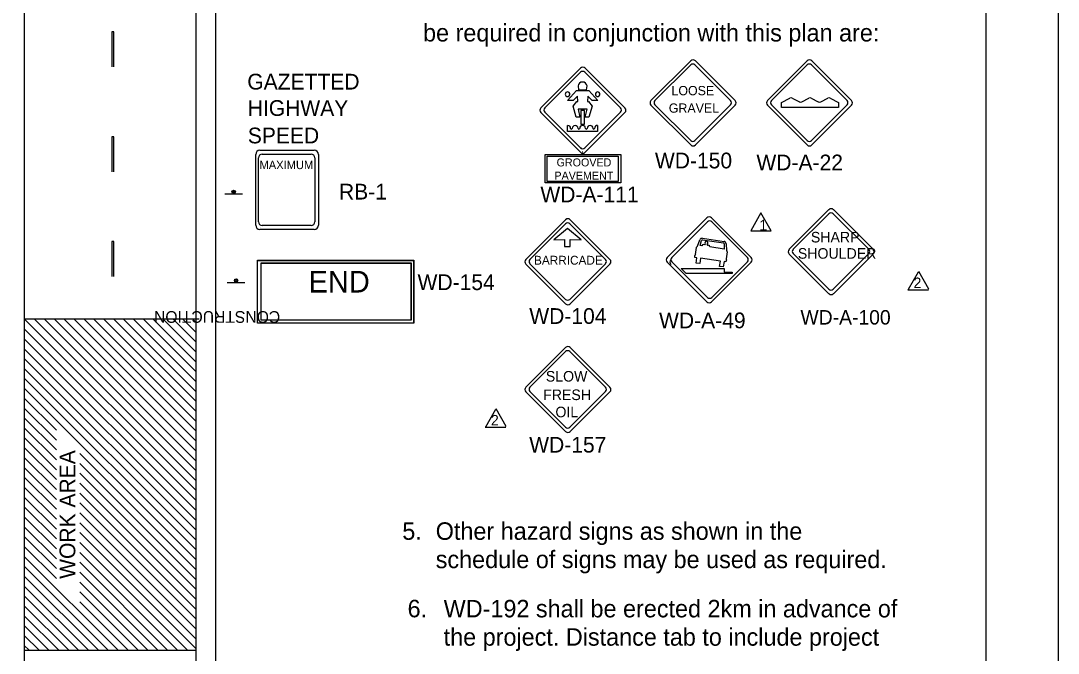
# Model space of a CAD drawing. Extents: x 1372 to 1588, y 125 to 404.
# Drawn here: x 1444.6 to 1588.1, y 244.9 to 332.4 of the extents above; entities that cross this region are included whole.
import ezdxf

# ---------------------------------------------------------------- set-up
doc = ezdxf.new("R2010")
doc.units = 0
for name, color, linetype in [('Level 1', 7, 'Continuous'), ('Level 10', 7, 'Continuous'), ('Level 2', 7, 'Continuous'), ('Level 4', 7, 'Continuous'), ('Level 44', 7, 'Continuous'), ('Level 5', 7, 'Continuous'), ('Level 60', 7, 'Continuous'), ('Level 63', 7, 'Continuous')]:
    doc.layers.add(name, color=color, linetype=linetype)

msp = doc.modelspace()

# ---------------------------------------------------------------- linework, layer by layer
at = {"layer": 'Level 1'}
for p, q in [((1549.79, 321.06), (1550.93, 321.68)), ((1551.27, 321.68), (1552.25, 321.14)), ((1552.58, 321.14), (1553.56, 321.68)), ((1553.9, 321.68), (1554.87, 321.15)), ((1555.21, 321.15), (1556.19, 321.68)), ((1556.53, 321.68), (1557.67, 321.07)), ((1549.79, 320.37), (1549.79, 321.06)), ((1553.73, 320.37), (1549.79, 320.37)), ((1557.67, 320.37), (1553.73, 320.37)), ((1557.67, 321.07), (1557.67, 320.37)), ((1538.16, 301.17), (1538.47, 302.04)), ((1538.55, 301.26), (1538.7, 301.96)), ((1538.84, 302.28), (1541.83, 301.85)), ((1538.86, 302.06), (1541.75, 301.65)), ((1539.16, 301.38), (1539.01, 301.4)), ((1539.01, 301.4), (1539.01, 301.4)), ((1541.86, 301.51), (1541.83, 300.79)), ((1542.12, 301.53), (1542.17, 300.6)), ((1537.9, 300.03), (1538, 300.99)), ((1538.05, 301.1), (1538.16, 301.17)), ((1538.77, 301.22), (1538.55, 301.26)), ((1539.69, 301.3), (1539.54, 301.32)), ((1541.83, 300.79), (1539.87, 301.07)), ((1542.28, 300.39), (1542.11, 299.42)), ((1542.17, 300.6), (1542.26, 300.5)), ((1537.81, 299.62), (1537.81, 299.9)), ((1538.09, 299.59), (1537.81, 299.62)), ((1537.98, 298.84), (1538.09, 299.59)), ((1538.48, 298.77), (1537.98, 298.84)), ((1538.59, 299.52), (1538.48, 298.77)), ((1541.33, 299.13), (1538.59, 299.52)), ((1541.21, 298.38), (1541.33, 299.13)), ((1541.83, 299.06), (1541.71, 298.31)), ((1542.08, 299.02), (1541.83, 299.05)), ((1542.15, 299.28), (1542.08, 299.02)), ((1542.13, 299.32), (1542.15, 299.28)), ((1541.71, 298.31), (1541.21, 298.38))]:
    msp.add_line(p, q, dxfattribs=at)
for points in [[(1546.94, 305.79), (1545.52, 303.32), (1548.36, 303.32)], [(1542.95, 297.41), (1536.61, 297.41), (1535.92, 298.1), (1541.86, 298.1), (1541.86, 297.58), (1542.95, 297.58)]]:
    msp.add_lwpolyline(points, close=True, dxfattribs=at)
for centre, radius, start, end in [((1551.1, 321.37), 0.35, 61.3649, 118.2462), ((1553.73, 321.37), 0.35, 61.6364, 118.4879), ((1556.36, 321.37), 0.35, 61.8639, 118.2174), ((1552.41, 321.45), 0.35, 241.3895, 298.4822), ((1555.04, 321.46), 0.35, 241.6262, 298.2462), ((1538.79, 301.93), 0.344, 81.9388, 160.7571), ((1538.84, 301.92), 0.138, 81.9344, 167.2438), ((1538.98, 301.2), 0.206, 81.9281, 171.9074), ((1539.17, 301.45), 0.0688, 261.9205, 351.8582), ((1539.55, 301.39), 0.0688, 171.8828, 261.9459), ((1541.73, 301.52), 0.138, 356.6105, 81.9338), ((1541.78, 301.51), 0.344, 3.1113, 81.9386), ((1537.77, 300.04), 0.138, 304.1825, 354.8723), ((1538.13, 300.98), 0.138, 124.8259, 174.8703), ((1539.66, 301.1), 0.206, 351.9552, 81.9216), ((1542.15, 300.41), 0.138, 349.4832, 39.2839), ((1534.81, 298.99), 0.457, 135, 225.0349), ((1542.24, 299.4), 0.138, 169.4858, 215.1975)]:
    msp.add_arc(centre, radius, start, end, dxfattribs=at)
msp.add_ellipse((1539.39, 301.64), major_axis=(-0.035, -0.256), ratio=0.783636, start_param=0.628057, end_param=5.591652, dxfattribs=at)
at = {"layer": 'Level 10'}
for p, q in [((1445.05, 372.63), (1445.05, 157.87)), ((1468.76, 372.63), (1468.76, 157.87)), ((1471.51, 372.63), (1471.51, 202.79)), ((1445.05, 291.11), (1469.25, 291.11)), ((1445.05, 291.11), (1468.76, 267.4)), ((1446.42, 291.11), (1468.76, 268.77)), ((1447.79, 291.11), (1468.76, 270.14)), ((1449.16, 291.11), (1468.76, 271.5)), ((1450.53, 291.11), (1468.76, 272.87)), ((1451.89, 291.11), (1468.76, 274.24)), ((1453.26, 291.11), (1468.76, 275.61)), ((1454.63, 291.11), (1468.76, 276.98)), ((1456, 291.11), (1468.76, 278.35)), ((1457.37, 291.11), (1468.76, 279.72)), ((1458.74, 291.11), (1468.76, 281.08)), ((1460.11, 291.11), (1468.76, 282.45)), ((1461.47, 291.11), (1468.76, 283.82)), ((1462.84, 291.11), (1468.76, 285.19)), ((1464.21, 291.11), (1468.76, 286.56)), ((1465.58, 291.11), (1468.76, 287.93)), ((1466.95, 291.11), (1468.76, 289.3)), ((1468.32, 291.11), (1468.76, 290.67)), ((1445.05, 289.74), (1468.76, 266.03)), ((1445.05, 288.37), (1468.76, 264.66)), ((1445.05, 287), (1468.76, 263.29)), ((1445.05, 285.63), (1468.76, 261.93)), ((1445.05, 284.26), (1468.76, 260.56)), ((1445.05, 282.9), (1468.76, 259.19)), ((1445.05, 281.53), (1468.76, 257.82)), ((1445.05, 280.16), (1449.49, 275.72)), ((1445.05, 278.79), (1449.49, 274.35)), ((1445.05, 277.42), (1449.49, 272.99)), ((1445.05, 276.05), (1449.49, 271.62)), ((1445.05, 274.69), (1449.49, 270.25)), ((1445.05, 273.32), (1449.49, 268.88)), ((1445.05, 271.95), (1449.49, 267.51)), ((1452.71, 272.5), (1468.76, 256.45)), ((1445.05, 270.58), (1449.49, 266.14)), ((1452.71, 271.13), (1468.76, 255.08)), ((1445.05, 269.21), (1449.49, 264.77)), ((1452.71, 269.76), (1468.76, 253.71)), ((1452.71, 268.39), (1468.76, 252.34)), ((1445.05, 267.84), (1445.06, 267.83)), ((1445.05, 267.84), (1449.49, 263.4)), ((1452.71, 267.02), (1468.76, 250.97)), ((1445.05, 266.47), (1449.49, 262.04)), ((1452.71, 265.65), (1468.76, 249.61)), ((1445.05, 265.11), (1449.49, 260.67)), ((1452.71, 264.29), (1468.76, 248.24)), ((1445.05, 263.74), (1449.49, 259.3)), ((1452.71, 262.92), (1468.76, 246.87)), ((1445.05, 262.37), (1449.49, 257.93)), ((1452.71, 261.55), (1468.76, 245.5)), ((1445.05, 261), (1449.49, 256.56)), ((1452.71, 260.18), (1467.66, 245.24)), ((1445.05, 259.63), (1449.49, 255.19)), ((1452.71, 258.81), (1466.29, 245.24)), ((1445.05, 258.26), (1458.08, 245.24)), ((1445.05, 256.89), (1456.71, 245.24)), ((1452.71, 257.44), (1464.92, 245.24)), ((1445.05, 255.52), (1455.34, 245.24)), ((1452.71, 256.07), (1463.55, 245.24)), ((1445.05, 254.16), (1453.97, 245.24)), ((1452.71, 254.71), (1462.19, 245.24)), ((1445.05, 252.79), (1452.61, 245.24)), ((1452.71, 253.34), (1460.82, 245.24)), ((1445.05, 251.42), (1451.24, 245.24)), ((1452.71, 251.97), (1459.45, 245.24)), ((1445.05, 250.05), (1449.87, 245.24)), ((1445.05, 248.68), (1448.5, 245.24)), ((1445.05, 247.31), (1447.13, 245.24)), ((1445.05, 245.94), (1445.74, 245.26)), ((1445.16, 245.26), (1468.76, 245.26))]:
    msp.add_line(p, q, dxfattribs=at)
at = {"layer": 'Level 2'}
for p, q in [((1457.15, 330.85), (1457.15, 326.01)), ((1457.44, 330.85), (1457.15, 330.85)), ((1457.44, 326.01), (1457.44, 330.85)), ((1457.15, 316.33), (1457.15, 311.49)), ((1457.44, 316.33), (1457.15, 316.33)), ((1457.44, 311.49), (1457.44, 316.33)), ((1457.15, 301.82), (1457.15, 296.98)), ((1457.44, 301.82), (1457.15, 301.82)), ((1457.44, 296.98), (1457.44, 301.82))]:
    msp.add_line(p, q, dxfattribs=at)
for points in [[(1477.28, 299.25), (1498.94, 299.25), (1498.94, 290.55), (1477.28, 290.55)], [(1477.28, 299.22), (1498.87, 299.22), (1498.87, 290.55), (1477.28, 290.55)], [(1477.79, 298.86), (1498.56, 298.86), (1498.56, 290.95), (1477.79, 290.95)], [(1477.79, 298.83), (1498.5, 298.83), (1498.5, 290.94), (1477.79, 290.94)]]:
    msp.add_lwpolyline(points, close=True, dxfattribs=at)
at = {"layer": 'Level 4'}
for p, q in [((1521.64, 323.36), (1521.72, 322.82)), ((1522.81, 322.82), (1522.89, 323.36)), ((1522.89, 323.36), (1522.89, 323.36)), ((1520.18, 321.35), (1521.42, 322.71)), ((1521.54, 321.92), (1520.94, 321.35)), ((1521.42, 322.71), (1523.11, 322.71)), ((1521.6, 321.19), (1521.54, 321.92)), ((1521.72, 322.82), (1522.81, 322.82)), ((1522.99, 321.92), (1522.93, 321.19)), ((1523.6, 321.35), (1522.99, 321.92)), ((1523.11, 322.71), (1524.36, 321.35)), ((1520.94, 321.35), (1520.18, 321.35)), ((1520.94, 320.54), (1521.45, 321.19)), ((1521.4, 319.05), (1520.94, 320.54)), ((1521.45, 321.19), (1521.6, 321.19)), ((1522.88, 320.16), (1521.66, 320.16)), ((1521.66, 320.16), (1521.89, 319.05)), ((1522.64, 319.05), (1522.88, 320.16)), ((1522.93, 321.19), (1523.08, 321.19)), ((1523.08, 321.19), (1523.6, 320.54)), ((1523.6, 320.54), (1523.14, 319.05)), ((1524.36, 321.35), (1523.6, 321.35)), ((1521.89, 319.05), (1521.4, 319.05)), ((1522.54, 319.94), (1522, 319.94)), ((1522, 319.94), (1522, 318.07)), ((1522.54, 318.07), (1522.54, 319.94)), ((1523.14, 319.05), (1522.64, 319.05)), ((1520.19, 317.05), (1520.19, 317.89)), ((1522, 318.07), (1522.54, 318.07)), ((1524.34, 317.89), (1524.34, 317.05)), ((1524.34, 317.05), (1520.19, 317.05))]:
    msp.add_line(p, q, dxfattribs=at)
for centre, radius, start, end in [((1522.27, 323.27), 0.631, 7.9818, 172.0182), ((1520.18, 322.21), 0.31, 45, 225), ((1520.18, 322.21), 0.31, 45.001, 224.999), ((1520.18, 322.21), 0.31, 224.9986, 45.0014), ((1520.18, 322.21), 0.31, 224.999, 45.001), ((1524.36, 322.21), 0.31, 45, 225), ((1524.36, 322.21), 0.31, 45.001, 224.999), ((1524.36, 322.21), 0.31, 224.9986, 45.0014), ((1524.36, 322.21), 0.31, 224.999, 45.001), ((1520.72, 317.48), 0.109, 180, 0), ((1521.75, 317.48), 0.109, 180, 0), ((1522.27, 317.48), 0.407, 0.7691, 179.2309), ((1522.78, 317.48), 0.109, 180, 0), ((1523.3, 317.48), 0.407, 0.7691, 179.2309), ((1523.81, 317.48), 0.109, 180, 0), ((1524.33, 317.48), 0.407, 88.4721, 179.2361)]:
    msp.add_arc(centre, radius, start, end, dxfattribs=at)
for centre, end_param in [((1520.2, 317.48), 4.739059), ((1521.23, 317.48), 6.283185)]:
    msp.add_ellipse(centre, major_axis=(-0.407, 0), ratio=0.986667, start_param=3.141593, end_param=end_param, dxfattribs=at)
at = {"layer": 'Level 44'}
for p, q in [((1521.99, 325.8), (1516.5, 320.32)), ((1528.12, 320.32), (1522.64, 325.8)), ((1537.22, 326.81), (1531.72, 321.33)), ((1532.27, 321.32), (1537.22, 326.26)), ((1537.8, 326.26), (1542.74, 321.32)), ((1543.35, 321.33), (1537.87, 326.81)), ((1553.33, 326.81), (1547.83, 321.33)), ((1548.38, 321.32), (1553.33, 326.26)), ((1553.91, 326.26), (1558.85, 321.32)), ((1559.46, 321.33), (1553.98, 326.81)), ((1517.05, 320.31), (1521.99, 325.25)), ((1522.57, 325.25), (1527.51, 320.31)), ((1531.72, 320.68), (1537.22, 315.19)), ((1531.73, 320.68), (1531.72, 320.68)), ((1537.22, 315.8), (1532.27, 320.74)), ((1542.74, 320.74), (1537.8, 315.8)), ((1537.87, 315.19), (1543.35, 320.68)), ((1547.83, 320.68), (1553.33, 315.19)), ((1547.84, 320.68), (1547.83, 320.68)), ((1553.33, 315.8), (1548.38, 320.74)), ((1558.85, 320.74), (1553.91, 315.8)), ((1553.98, 315.19), (1559.46, 320.68)), ((1516.5, 319.67), (1521.99, 314.18)), ((1516.5, 319.67), (1516.5, 319.67)), ((1521.99, 314.79), (1517.05, 319.73)), ((1527.51, 319.73), (1522.57, 314.79)), ((1522.64, 314.18), (1528.12, 319.67)), ((1477.63, 314.46), (1485.14, 314.46)), ((1477.05, 304.08), (1477.05, 313.88)), ((1477.43, 304.57), (1477.43, 313.39)), ((1477.95, 313.92), (1484.72, 313.92)), ((1485.24, 313.39), (1485.24, 304.57)), ((1485.72, 313.88), (1485.72, 304.08)), ((1472.79, 308.42), (1475.21, 308.42)), ((1556.33, 306.24), (1550.83, 300.75)), ((1551.38, 300.75), (1556.33, 305.68)), ((1556.91, 305.68), (1561.85, 300.75)), ((1562.46, 300.75), (1556.98, 306.24)), ((1477.43, 304.57), (1477.43, 304.57)), ((1519.92, 304.84), (1514.42, 299.35)), ((1514.97, 299.35), (1519.92, 304.29)), ((1514.97, 299.35), (1519.92, 304.29)), ((1514.97, 299.35), (1519.92, 304.29)), ((1520.5, 304.29), (1525.44, 299.35)), ((1520.5, 304.29), (1525.44, 299.35)), ((1520.5, 304.29), (1525.44, 299.35)), ((1526.05, 299.35), (1520.57, 304.84)), ((1539.45, 305.11), (1533.96, 299.63)), ((1534.6, 299.62), (1539.54, 304.56)), ((1545.59, 299.63), (1540.1, 305.11)), ((1540.12, 304.56), (1545.06, 299.62)), ((1477.05, 304.07), (1477.05, 304.08)), ((1485.14, 303.5), (1477.63, 303.5)), ((1477.76, 303.74), (1477.76, 303.74)), ((1484.72, 304.05), (1477.95, 304.05)), ((1520.16, 303.64), (1518.27, 302.05)), ((1520.16, 303.64), (1518.27, 302.05)), ((1520.16, 303.64), (1518.27, 302.05)), ((1522.05, 302.05), (1520.16, 303.64)), ((1522.05, 302.05), (1520.16, 303.64)), ((1522.05, 302.05), (1520.16, 303.64)), ((1518.27, 302.05), (1519.78, 302.13)), ((1518.27, 302.05), (1519.78, 302.13)), ((1518.27, 302.05), (1519.78, 302.13)), ((1519.78, 302.13), (1519.78, 301.12)), ((1519.78, 302.13), (1519.78, 301.12)), ((1519.78, 302.13), (1519.78, 301.12)), ((1520.54, 301.12), (1520.54, 302.13)), ((1520.54, 302.13), (1522.05, 302.05)), ((1520.54, 301.12), (1520.54, 302.13)), ((1520.54, 302.13), (1522.05, 302.05)), ((1520.54, 301.12), (1520.54, 302.13)), ((1520.54, 302.13), (1522.05, 302.05)), ((1539.23, 301.44), (1539.24, 301.46)), ((1539.48, 301.42), (1539.48, 301.41)), ((1519.78, 301.12), (1520.53, 301.12)), ((1519.78, 301.12), (1520.53, 301.12)), ((1519.78, 301.12), (1520.53, 301.12)), ((1537.84, 299.92), (1537.81, 299.9)), ((1550.83, 300.1), (1556.33, 294.61)), ((1550.84, 300.1), (1550.83, 300.1)), ((1556.33, 295.22), (1551.38, 300.16)), ((1561.85, 300.16), (1556.91, 295.22)), ((1556.98, 294.61), (1562.46, 300.1)), ((1514.42, 298.7), (1519.92, 293.21)), ((1514.43, 298.7), (1514.42, 298.7)), ((1519.92, 293.82), (1514.97, 298.76)), ((1519.92, 293.82), (1514.97, 298.76)), ((1519.92, 293.82), (1514.97, 298.76)), ((1525.44, 298.76), (1520.5, 293.82)), ((1525.44, 298.76), (1520.5, 293.82)), ((1525.44, 298.76), (1520.5, 293.82)), ((1520.57, 293.21), (1526.05, 298.7)), ((1533.96, 298.98), (1539.45, 293.48)), ((1533.96, 298.98), (1533.96, 298.98)), ((1539.54, 294.09), (1534.6, 299.04)), ((1540.1, 293.48), (1545.59, 298.98)), ((1545.06, 299.04), (1540.12, 294.09)), ((1542.39, 298.62), (1542.39, 298.62)), ((1473.12, 296.16), (1475.54, 296.16)), ((1519.92, 287.15), (1514.42, 281.67)), ((1526.05, 281.67), (1520.57, 287.15)), ((1514.97, 281.66), (1519.92, 286.6)), ((1520.5, 286.6), (1525.44, 281.66)), ((1514.42, 281.01), (1519.92, 275.52)), ((1514.43, 281.01), (1514.42, 281.01)), ((1519.92, 276.13), (1514.97, 281.07)), ((1525.44, 281.07), (1520.5, 276.13)), ((1520.57, 275.52), (1526.05, 281.01))]:
    msp.add_line(p, q, dxfattribs=at)
msp.add_lwpolyline([(1542.28, 300.38), (1542.29, 300.38)], dxfattribs=at)
for centre, radius in [((1474, 308.69), 0.242), ((1474, 308.69), 0.121), ((1474.34, 296.43), 0.242), ((1474.34, 296.43), 0.121)]:
    msp.add_circle(centre, radius, dxfattribs=at)
for centre, radius, start, end in [((1522.31, 325.48), 0.459, 45, 135), ((1537.54, 326.49), 0.459, 45, 135), ((1537.51, 325.97), 0.413, 45, 135), ((1553.65, 326.49), 0.459, 45, 135), ((1553.62, 325.97), 0.413, 45, 135), ((1522.28, 324.96), 0.413, 45, 135), ((1516.82, 319.99), 0.459, 135, 225), ((1517.34, 320.02), 0.413, 135, 225), ((1527.22, 320.02), 0.413, 315, 45), ((1527.8, 319.99), 0.459, 315, 45), ((1532.05, 321), 0.459, 135, 225), ((1532.57, 321.03), 0.413, 135, 225), ((1542.45, 321.03), 0.413, 315, 45), ((1543.03, 321), 0.459, 315, 45), ((1548.16, 321), 0.459, 135, 225), ((1548.68, 321.03), 0.413, 135, 225), ((1558.56, 321.03), 0.413, 315, 45), ((1559.14, 321), 0.459, 315, 45), ((1537.51, 316.09), 0.413, 225, 315), ((1553.62, 316.09), 0.413, 225, 315), ((1477.63, 313.88), 0.58, 90, 180), ((1485.14, 313.88), 0.58, 360, 90), ((1522.28, 315.08), 0.413, 225, 315), ((1537.54, 315.51), 0.459, 225, 315), ((1553.65, 315.51), 0.459, 225, 315), ((1477.96, 313.39), 0.522, 90, 180), ((1484.72, 313.39), 0.522, 360, 90), ((1522.31, 314.5), 0.459, 225, 315), ((1556.65, 305.91), 0.459, 45, 135), ((1556.62, 305.39), 0.413, 45, 135), ((1477.96, 304.57), 0.522, 180, 270), ((1484.72, 304.57), 0.522, 270, 360), ((1520.24, 304.52), 0.459, 45, 135), ((1520.21, 303.99), 0.413, 45, 135), ((1520.21, 303.99), 0.413, 45, 135), ((1520.21, 303.99), 0.413, 45, 135), ((1539.77, 304.79), 0.459, 45, 135), ((1539.83, 304.27), 0.413, 45, 135), ((1477.63, 304.07), 0.58, 180, 270), ((1485.14, 304.07), 0.58, 270, 360), ((1551.16, 300.42), 0.459, 135, 225), ((1551.68, 300.45), 0.413, 135, 225), ((1561.56, 300.45), 0.413, 315, 45), ((1562.14, 300.42), 0.459, 315, 45), ((1514.75, 299.03), 0.459, 135, 225), ((1515.27, 299.06), 0.413, 135, 225), ((1515.27, 299.06), 0.413, 135, 225), ((1515.27, 299.06), 0.413, 135, 225), ((1525.15, 299.06), 0.413, 315, 45), ((1525.15, 299.06), 0.413, 315, 45), ((1525.15, 299.06), 0.413, 315, 45), ((1525.73, 299.03), 0.459, 315, 45), ((1534.28, 299.3), 0.459, 135, 225), ((1534.89, 299.33), 0.413, 135, 225), ((1544.77, 299.33), 0.413, 315, 45), ((1545.26, 299.3), 0.459, 315, 45), ((1556.62, 295.51), 0.413, 225, 315), ((1556.65, 294.94), 0.459, 225, 315), ((1520.21, 294.12), 0.413, 225, 315), ((1520.21, 294.12), 0.413, 225, 315), ((1520.21, 294.12), 0.413, 225, 315), ((1520.24, 293.54), 0.459, 225, 315), ((1539.77, 293.81), 0.459, 225, 315), ((1539.83, 294.39), 0.413, 225, 315), ((1520.24, 286.83), 0.459, 45, 135), ((1520.21, 286.31), 0.413, 45, 135), ((1514.75, 281.34), 0.459, 135, 225), ((1515.27, 281.37), 0.413, 135, 225), ((1525.15, 281.37), 0.413, 315, 45), ((1525.73, 281.34), 0.459, 315, 45), ((1520.21, 276.43), 0.413, 225, 315), ((1520.24, 275.85), 0.459, 225, 315)]:
    msp.add_arc(centre, radius, start, end, dxfattribs=at)
at = {"layer": 'Level 5'}
for p, q in [((1522.08, 314.76), (1522.13, 314.76)), ((1522.13, 314.76), (1522.08, 314.76)), ((1522.13, 314.76), (1522.13, 314.76)), ((1522.24, 314.22), (1522.29, 314.22)), ((1522.29, 314.22), (1522.24, 314.22)), ((1522.29, 314.22), (1522.29, 314.22))]:
    msp.add_line(p, q, dxfattribs=at)
for points in [[(1517.08, 313.88), (1527.54, 313.88), (1527.54, 309.97), (1517.08, 309.97)], [(1517.36, 313.66), (1527.19, 313.66), (1527.19, 310.14), (1517.36, 310.14)]]:
    msp.add_lwpolyline(points, close=True, dxfattribs=at)
for centre in [(1522.1, 314.79), (1522.27, 314.25)]:
    msp.add_arc(centre, 0.0341, 225, 315, dxfattribs=at)
at = {"layer": 'Level 60'}
for points in [[(1372.06, 403.98), (1588.06, 403.98), (1588.06, 124.98), (1372.06, 124.98)], [(1391.18, 393.17), (1578.06, 393.17), (1578.06, 135.79), (1391.18, 135.79)]]:
    msp.add_lwpolyline(points, close=True, dxfattribs=at)
at = {"layer": 'Level 63'}
for points in [[(1568.67, 297.59), (1567.28, 295.17)], [(1570.15, 295.24), (1568.76, 297.67)], [(1567.28, 295.17), (1567.25, 295.12), (1570.09, 295.12), (1570.06, 295.17)], [(1510.21, 278.59), (1508.82, 276.16)], [(1511.7, 276.24), (1510.3, 278.66)], [(1508.82, 276.16), (1508.79, 276.12), (1511.63, 276.12), (1511.61, 276.16)]]:
    msp.add_lwpolyline(points, dxfattribs=at)

# ---------------------------------------------------------------- texts
at = {"layer": 'Level 1'}
msp.add_text('1', height=1.45, rotation=360, dxfattribs=at).set_placement((1546.72, 303.38))
at = {"layer": 'Level 10'}
for s, height, p in [('be required in conjunction with this plan are:', 2.419, (1500.2, 329.51)), ('WD-A-49', 2.178, (1532.84, 289.82)), ('5.', 2.419, (1497.33, 260.55)), ('Other hazard signs as shown in the', 2.419, (1501.95, 260.55)), ('schedule of signs may be used as required.       ', 2.419, (1501.95, 256.63)), ('6.', 2.419, (1498.06, 249.83)), ('WD-192 shall be erected 2km in advance of ', 2.419, (1503.05, 249.82)), ('the project. Distance tab to include project ', 2.419, (1503.05, 245.9))]:
    msp.add_text(s, height=height, dxfattribs=at).set_placement(p)
for s, height, rotation, p in [('GAZETTED', 2.177, 360, (1475.89, 322.86)), ('HIGHWAY', 2.177, 360, (1475.95, 319.21)), ('SPEED', 2.177, 360, (1475.96, 315.41)), ('WD-150', 2.177, 360, (1532.27, 311.95)), ('WD-A-22', 2.177, 360, (1546.31, 311.68)), ('RB-1', 2.177, 360, (1488.57, 307.64)), ('WD-A-111', 2.177, 360, (1516.43, 307.25)), ('WD-154', 2.177, 360, (1499.44, 295.11)), ('WD-104', 2.177, 360, (1514.89, 290.43)), ('WD-157', 2.177, 360, (1514.88, 272.62)), ('WORK AREA', 2.178, 90, (1452.1, 255.15))]:
    msp.add_text(s, height=height, rotation=rotation, dxfattribs=at).set_placement(p)
at = {"layer": 'Level 44'}
for s, height, rotation, p in [('LOOSE', 1.282, 360, (1534.56, 322.07)), ('GRAVEL', 1.282, 360, (1534.19, 319.65)), ('MAXIMUM', 1.15, 360, (1477.58, 311.85)), ('SHARP', 1.461, 360, (1553.84, 301.7)), ('SHOULDER', 1.461, 360, (1552.04, 299.45)), ('BARRICADE', 1.218, 360, (1515.55, 298.63)), ('BARRICADE', 1.218, 360, (1515.55, 298.63)), ('BARRICADE', 1.218, 360, (1515.55, 298.63)), ('END', 3, 360, (1484.36, 294.77)), ('2', 1.45, 360, (1568.04, 295.39)), ('CONSTRUCTION', 1.62, 180, (1480.44, 292.2)), ('SLOW', 1.461, 360, (1517.18, 282.45)), ('FRESH', 1.461, 360, (1516.81, 279.89)), ('OIL', 1.461, 360, (1518.51, 277.51)), ('2', 1.45, 360, (1509.59, 276.38))]:
    msp.add_text(s, height=height, rotation=rotation, dxfattribs=at).set_placement(p)
msp.add_text('WD-A-100      ', height=1.999, dxfattribs=at).set_placement((1552.4, 290.34))
at = {"layer": 'Level 5'}
for s, p in [('GROOVED', (1518.67, 312.22)), ('PAVEMENT', (1518.37, 310.39))]:
    msp.add_text(s, height=1.108, dxfattribs=at).set_placement(p)

doc.saveas('drawing.dxf')
